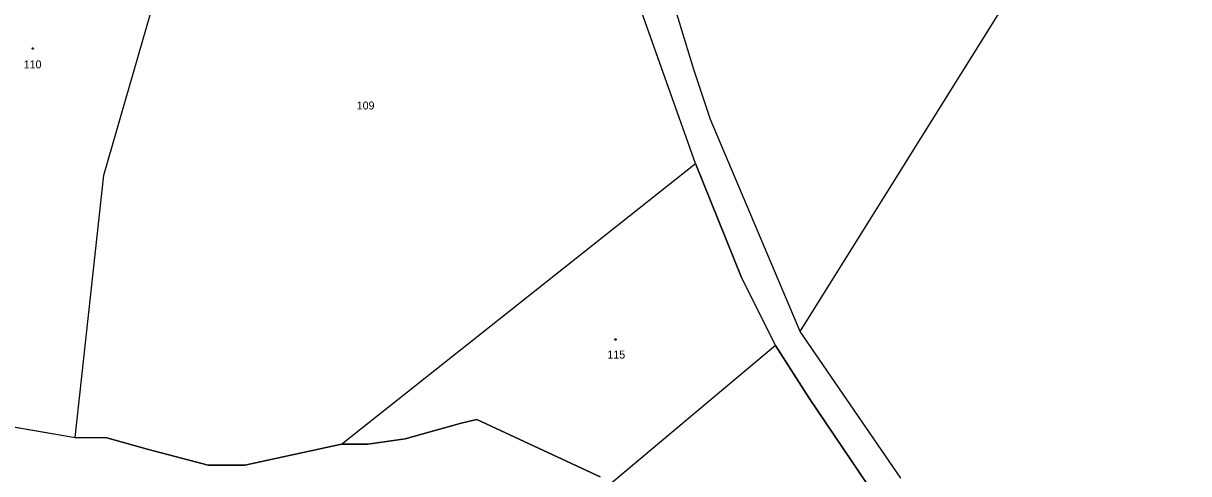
# Model space of a CAD drawing. Extents: x -841286 to -834997, y -1020681 to -1017810.
# Drawn here: x -838632.6 to -838385, y -1019442.2 to -1019346.4 of the extents above; entities that cross this region are included whole.
import ezdxf

# ---------------------------------------------------------------- set-up
doc = ezdxf.new("R2010")
doc.units = 0
for name, color, linetype in [('OVNE_POP', 7, 'Continuous'), ('OVNE_PRE', 7, 'Continuous'), ('OVNE_SET', 7, 'Continuous'), ('OVNI_SET', 7, 'Continuous')]:
    doc.layers.add(name, color=color, linetype=linetype)

msp = doc.modelspace()

# ---------------------------------------------------------------- linework, layer by layer
at = {"layer": 'OVNE_POP'}
for points in [[(-838630.48, -1019351.63), (-838630.39, -1019351.78), (-838630.48, -1019351.93), (-838630.66, -1019351.93), (-838630.75, -1019351.78), (-838630.66, -1019351.63)], [(-838506.69, -1019413.52), (-838506.6, -1019413.67), (-838506.69, -1019413.82), (-838506.87, -1019413.82), (-838506.96, -1019413.67), (-838506.87, -1019413.52)]]:
    msp.add_lwpolyline(points, close=True, dxfattribs=at)
at = {"layer": 'OVNE_SET'}
for p, q in [((-838467.55, -1019411.98), (-838342.17, -1019210.92)), ((-838615.45, -1019378.71), (-838592.81, -1019300.12)), ((-838489.78, -1019376.26), (-838516.57, -1019300.78)), ((-838490.15, -1019356.24), (-838493.94, -1019343.74)), ((-838486.58, -1019366.9), (-838490.15, -1019356.24)), ((-838467.55, -1019411.98), (-838486.58, -1019366.9)), ((-838565, -1019435.94), (-838489.78, -1019376.26)), ((-838489.78, -1019376.26), (-838480.03, -1019400.47)), ((-838621.56, -1019434.51), (-838615.45, -1019378.71)), ((-838480.03, -1019400.47), (-838472.78, -1019414.95)), ((-838446.15, -1019443.19), (-838467.55, -1019411.98)), ((-838472.78, -1019414.95), (-838509.33, -1019445.67)), ((-838472.78, -1019414.95), (-838465.61, -1019426.16)), ((-838465.61, -1019426.16), (-838428.88, -1019480.59)), ((-838638.75, -1019431.56), (-838621.56, -1019434.51)), ((-838539.55, -1019431.48), (-838551.47, -1019434.81)), ((-838536.25, -1019430.7), (-838539.55, -1019431.48)), ((-838510.07, -1019442.9), (-838536.25, -1019430.7)), ((-838614.81, -1019434.56), (-838621.56, -1019434.51)), ((-838606, -1019437.1), (-838614.81, -1019434.56)), ((-838551.47, -1019434.81), (-838559.4, -1019435.95)), ((-838593.35, -1019440.42), (-838606, -1019437.1)), ((-838565, -1019435.94), (-838585.55, -1019440.4)), ((-838559.4, -1019435.95), (-838565, -1019435.94)), ((-838585.55, -1019440.4), (-838593.35, -1019440.42))]:
    msp.add_line(p, q, dxfattribs=at)
at = {"layer": 'OVNI_SET'}
for points in [[(-838428.88, -1019480.59), (-838465.61, -1019426.16), (-838472.78, -1019414.95), (-838480.03, -1019400.47), (-838489.78, -1019376.26), (-838516.57, -1019300.78)], [(-838776.24, -1019441.54), (-838761.34, -1019420.24), (-838709.81, -1019424.05), (-838655.6, -1019428.68), (-838638.75, -1019431.56), (-838621.56, -1019434.51), (-838614.81, -1019434.56), (-838606, -1019437.1), (-838593.35, -1019440.42), (-838585.55, -1019440.4), (-838565, -1019435.94), (-838559.4, -1019435.95), (-838551.47, -1019434.81), (-838539.55, -1019431.48), (-838536.25, -1019430.7), (-838510.07, -1019442.9)]]:
    msp.add_lwpolyline(points, dxfattribs=at)

# ---------------------------------------------------------------- texts
at = {"layer": 'OVNE_PRE'}
for s, p in [('110', (-838632.52, -1019356.02)), ('109', (-838561.77, -1019364.76)), ('115', (-838508.51, -1019417.73))]:
    msp.add_text(s, height=1.7, dxfattribs=at).set_placement(p)

doc.saveas('drawing.dxf')
